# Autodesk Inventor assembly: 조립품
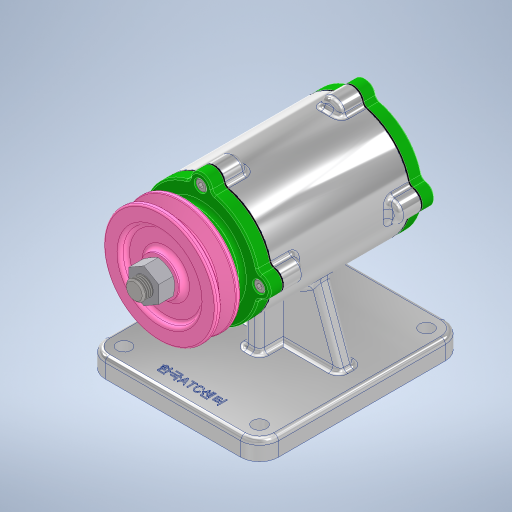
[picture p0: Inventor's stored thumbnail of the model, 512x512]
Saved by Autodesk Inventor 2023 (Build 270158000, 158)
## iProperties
Created: 2023-08
Part Number: 조립품
Document SubType Name: Assembly
Designer: asung
Author: asung
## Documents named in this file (12)
- C:\Users\asung\Desktop\730808V1010\조립품.iam
- C:\Users\asung\Desktop\730808V1010\본체.ipt
- C:\Users\asung\Desktop\730808V1010\개스킷.ipt
- C:\Users\asung\Desktop\730808V1010\앞커버.ipt
- C:\Users\asung\Desktop\730808V1010\뒤커버.ipt
- C:\Users\asung\Desktop\730808V1010\축.ipt
- C:\Users\asung\Desktop\730808V1010\베어링 6204.ipt
- C:\Users\asung\Desktop\730808V1010\볼트 M4 x 12.ipt
- C:\Users\asung\Desktop\730808V1010\키 4 x 4.ipt
- C:\Users\asung\Desktop\730808V1010\V-벨트풀리.ipt
- C:\Users\asung\Desktop\730808V1010\너트 M12 x 1.25.ipt
- C:\Users\asung\Desktop\730808V1010\오일 실.ipt
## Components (8 placed, 6 different names)
1. 개스킷:1
2. 개스킷:2
3. KS B 2023 6204 - 20 x 47 x 14:1
4. KS B 2023 6204 - 20 x 47 x 14:2
5. KS B 1311 (I) 4 x 4 x 12:1
6. V-벨트풀리:1
7. KS B 1012 클래스 1 일반 - 미터 M12x1.25:1
8. KS B 2804 D D - 20 32 8:1
